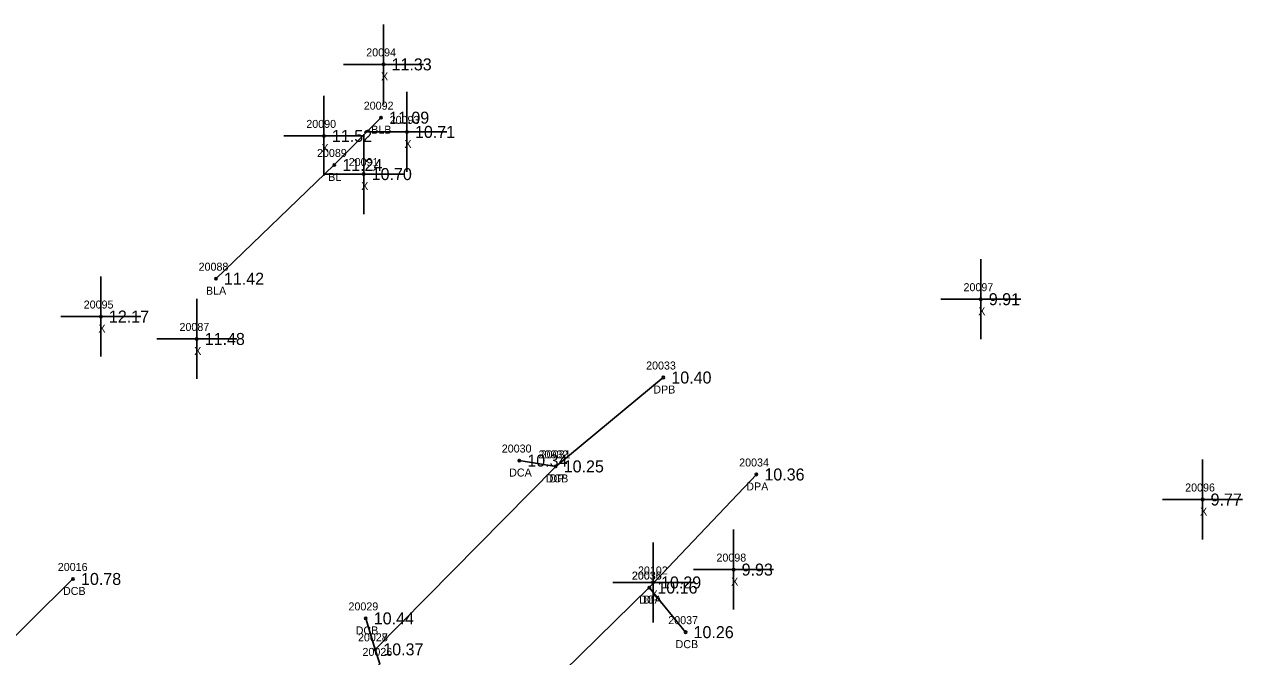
# Model space of a CAD drawing. Extents: x 2608745 to 2610333, y 641917 to 643463.
# Drawn here: x 2608842.3 to 2608994.6, y 643383.8 to 643462.8 of the extents above; entities that cross this region are included whole.
import ezdxf

# ---------------------------------------------------------------- set-up
doc = ezdxf.new("R2010")
doc.units = 0
for name, color, linetype in [('RD_DTM_BkLn1', 7, 'Continuous'), ('RD_DTM_BkLn_txCode', 7, 'Continuous'), ('RD_EX_Conc', 7, 'Continuous'), ('RD_EX_Conc_txCode', 7, 'Continuous'), ('RD_EX_Driveway', 7, 'Continuous'), ('RD_EX_Driveway_txCode', 7, 'Continuous'), ('RD_EX_Misc', 7, 'Continuous'), ('RD_EX_Misc_txCode', 7, 'Continuous'), ('RD_EX_TX_Conc_ELEV', 7, 'Continuous'), ('RD_EX_TX_Driveway_ELEV', 7, 'Continuous'), ('RD_EX_TX_Misc_ELEV', 7, 'Continuous'), ('RD_SMD_Locator', 7, 'Continuous')]:
    doc.layers.add(name, color=color, linetype=linetype)

msp = doc.modelspace()

# ---------------------------------------------------------------- linework, layer by layer
at = {"layer": 'RD_DTM_BkLn1'}
msp.add_lwpolyline([(2608866.24, 643431.05), (2608881.04, 643445.27), (2608886.88, 643451.18)], dxfattribs=at)
at = {"layer": 'RD_EX_Conc'}
for p, q in [((2608904.16, 643408.32), (2608908.71, 643407.59)), ((2608920.41, 643392.44), (2608924.94, 643386.87)), ((2608886.16, 643384.72), (2608884.97, 643388.59))]:
    msp.add_line(p, q, dxfattribs=at)
msp.add_lwpolyline([(2608829.58, 643376.81), (2608831.9, 643377.24), (2608848.38, 643393.52)], dxfattribs=at)
at = {"layer": 'RD_EX_Driveway'}
for points in [[(2608852.07, 643354.1), (2608857.77, 643354.47), (2608865.25, 643359.71), (2608886.74, 643382.9), (2608886.16, 643384.72), (2608908.71, 643407.59), (2608922.16, 643418.7)], [(2608933.79, 643406.58), (2608920.41, 643392.44), (2608898.88, 643371.38), (2608887.45, 643360.52), (2608881.77, 643355.12), (2608872.92, 643346.71), (2608873.12, 643334.61)]]:
    msp.add_lwpolyline(points, dxfattribs=at)
at = {"layer": 'RD_EX_Misc'}
for p, q in [((2608887.19, 643452.84), (2608887.19, 643462.84)), ((2608882.19, 643457.84), (2608892.19, 643457.84)), ((2608879.74, 643443.9), (2608879.74, 643453.9)), ((2608890.12, 643444.4), (2608890.12, 643454.4)), ((2608884.71, 643439.13), (2608884.71, 643449.13)), ((2608885.12, 643449.4), (2608895.12, 643449.4)), ((2608874.74, 643448.9), (2608884.74, 643448.9)), ((2608879.71, 643444.13), (2608889.71, 643444.13)), ((2608961.84, 643423.49), (2608961.84, 643433.49)), ((2608851.87, 643421.32), (2608851.87, 643431.32)), ((2608863.84, 643418.52), (2608863.84, 643428.52)), ((2608956.84, 643428.49), (2608966.84, 643428.49)), ((2608846.87, 643426.32), (2608856.87, 643426.32)), ((2608858.84, 643423.52), (2608868.84, 643423.52)), ((2608989.56, 643398.45), (2608989.56, 643408.45)), ((2608984.56, 643403.45), (2608994.56, 643403.45)), ((2608930.95, 643389.69), (2608930.95, 643399.69)), ((2608920.87, 643388.08), (2608920.87, 643398.08)), ((2608925.95, 643394.69), (2608935.95, 643394.69)), ((2608915.87, 643393.08), (2608925.87, 643393.08))]:
    msp.add_line(p, q, dxfattribs=at)
at = {"layer": 'RD_SMD_Locator'}
for centre in [(2608887.19, 643457.84), (2608886.88, 643451.18), (2608879.74, 643448.9), (2608890.12, 643449.4), (2608881.04, 643445.27), (2608884.71, 643444.13), (2608866.24, 643431.05), (2608961.84, 643428.49), (2608851.87, 643426.32), (2608863.84, 643423.52), (2608922.16, 643418.7), (2608904.16, 643408.32), (2608908.71, 643407.59), (2608908.71, 643407.59), (2608933.79, 643406.58), (2608989.56, 643403.45), (2608930.95, 643394.69), (2608848.38, 643393.52), (2608920.41, 643392.44), (2608920.41, 643392.44), (2608920.87, 643393.08), (2608884.97, 643388.59), (2608924.94, 643386.87), (2608886.16, 643384.72), (2608886.16, 643384.72)]:
    msp.add_circle(centre, 0.15, dxfattribs=at)

# ---------------------------------------------------------------- texts
at = {"layer": 'RD_DTM_BkLn_txCode'}
for s, p in [('20092', (2608884.72, 643452.18)), ('BLB', (2608885.65, 643449.18)), ('20089', (2608878.88, 643446.27)), ('BL', (2608880.28, 643443.27)), ('20088', (2608864.08, 643432.05)), ('BLA', (2608865, 643429.05))]:
    msp.add_text(s, height=1, dxfattribs=at).set_placement(p)
at = {"layer": 'RD_EX_Conc_txCode'}
for s, p in [('20030', (2608901.97, 643409.32)), ('20031', (2608906.84, 643408.59)), ('DCA', (2608902.89, 643406.32)), ('DCB', (2608907.46, 643405.59)), ('20016', (2608846.48, 643394.52)), ('20036', (2608918.22, 643393.44)), ('DCB', (2608847.13, 643391.52)), ('DCA', (2608919.14, 643390.44)), ('20029', (2608882.81, 643389.59)), ('20037', (2608922.78, 643387.87)), ('DCB', (2608883.71, 643386.59)), ('20028', (2608884, 643385.72)), ('DCB', (2608923.69, 643384.87))]:
    msp.add_text(s, height=1, dxfattribs=at).set_placement(p)
at = {"layer": 'RD_EX_Driveway_txCode'}
for s, p in [('20033', (2608920.01, 643419.7)), ('DPB', (2608920.91, 643416.7)), ('20032', (2608906.56, 643408.59)), ('20034', (2608931.64, 643407.58)), ('DP', (2608907.94, 643405.59)), ('DPA', (2608932.53, 643404.58)), ('20035', (2608918.25, 643393.44)), ('DP', (2608919.63, 643390.44)), ('20027', (2608884, 643385.72)), ('20026', (2608884.56, 643383.9))]:
    msp.add_text(s, height=1, dxfattribs=at).set_placement(p)
at = {"layer": 'RD_EX_Misc_txCode'}
for s, p in [('20094', (2608885.03, 643458.84)), ('X', (2608886.88, 643455.84)), ('20090', (2608877.54, 643449.9)), ('20093', (2608887.96, 643450.4)), ('X', (2608879.43, 643446.9)), ('X', (2608889.8, 643447.4)), ('20091', (2608882.84, 643445.13)), ('X', (2608884.4, 643442.13)), ('20097', (2608959.68, 643429.49)), ('20095', (2608849.72, 643427.32)), ('X', (2608961.53, 643426.49)), ('X', (2608851.56, 643424.32)), ('20087', (2608861.69, 643424.52)), ('X', (2608863.53, 643421.52)), ('20096', (2608987.38, 643404.45)), ('X', (2608989.25, 643401.45)), ('20098', (2608928.8, 643395.69)), ('20102', (2608918.99, 643394.08)), ('X', (2608930.64, 643392.69)), ('X', (2608920.55, 643391.08))]:
    msp.add_text(s, height=1, dxfattribs=at).set_placement(p)
at = {"layer": 'RD_EX_TX_Conc_ELEV'}
for s, p in [('10.34', (2608905.16, 643407.57)), ('10.25', (2608909.71, 643406.84)), ('10.78', (2608849.38, 643392.77)), ('10.16', (2608921.41, 643391.69)), ('10.44', (2608885.97, 643387.84)), ('10.26', (2608925.94, 643386.12)), ('10.37', (2608887.16, 643383.97))]:
    msp.add_text(s, height=1.5, dxfattribs=at).set_placement(p)
at = {"layer": 'RD_EX_TX_Driveway_ELEV'}
for s, p in [('10.40', (2608923.16, 643417.95)), ('10.25', (2608909.71, 643406.84)), ('10.36', (2608934.79, 643405.83)), ('10.16', (2608921.41, 643391.69)), ('10.37', (2608887.16, 643383.97))]:
    msp.add_text(s, height=1.5, dxfattribs=at).set_placement(p)
at = {"layer": 'RD_EX_TX_Misc_ELEV'}
for s, p in [('11.33', (2608888.19, 643457.09)), ('11.09', (2608887.88, 643450.43)), ('11.52', (2608880.74, 643448.15)), ('10.71', (2608891.12, 643448.65)), ('11.24', (2608882.04, 643444.52)), ('10.70', (2608885.71, 643443.38)), ('11.42', (2608867.24, 643430.3)), ('9.91', (2608962.84, 643427.74)), ('12.17', (2608852.87, 643425.57)), ('11.48', (2608864.84, 643422.77)), ('9.77', (2608990.56, 643402.7)), ('9.93', (2608931.95, 643393.94)), ('10.29', (2608921.87, 643392.33))]:
    msp.add_text(s, height=1.5, dxfattribs=at).set_placement(p)

doc.saveas('drawing.dxf')
